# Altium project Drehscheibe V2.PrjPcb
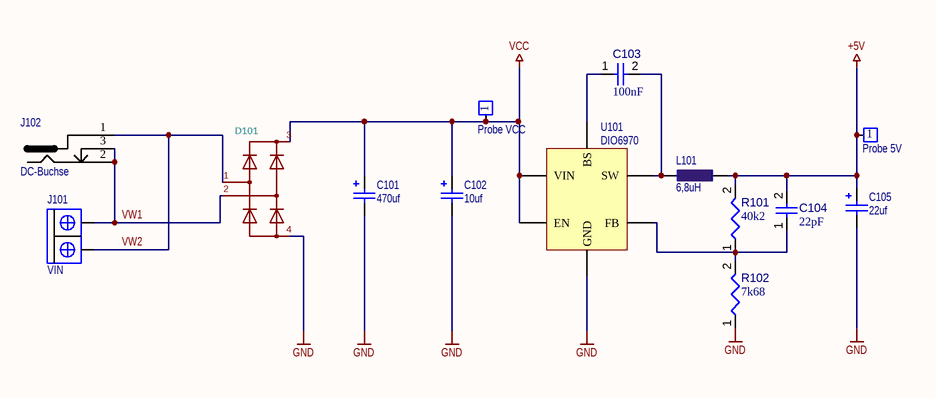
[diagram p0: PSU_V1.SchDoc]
7 sheets, 75 parts. Net scope: global (net labels, ports and power ports of the same name join across sheets).
Board file: Drehscheibe_V1.PcbDoc
Sheets:
  PSU_V1.SchDoc
  uC_V1.SchDoc
  Display_V1.SchDoc
  Stepper_V1.SchDoc
  Demudulation_V1.SchDoc
  Relais und Connector_V1.SchDoc
  Bediehneinheit_V1.SchDoc

## Sheet PSU_V1.SchDoc
size A4; SheetNumber: 1; SheetTotal: 7

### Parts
C101  470uf  [C_SMD_F-TYP]
C102  10uf  [C_SMD_C-TYP]
C103  value 100nF  [CAPC1608X90X40NL10T20]  (hidden comment: Capacitor 100 nF +/-10% 50 V 0603)
C104  22pF  [CAPC1608X90X40NL10T20]
C105  22uf  [C_SMD_C-TYP]
D101  *3D Model may have slightly different dimensions  [SO-DIL-ABS-4mm]  (value not drawn)
J101  VIN  [J_THT_Printklemme 2x]
J102  DC-Buchse  [J_THT_CJ-25]
L101  6,8uH  [L_SMD_NPIS42LS]
Probe_5V  #Wert  [SIP-1]  (value not drawn)
Probe_VCC  #Wert  [SIP-1]  (value not drawn)
R101  40k2  [RESC1608X55X25ML10T15]
R102  7k68  [RESC1608X55X25ML10T15]
U101  DIO6970  [SOT23-6]

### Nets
+5V: C104.2 C105.1 L101.1 Probe_5V.1 R101.2
GND: C101.2 C102.2 C105.2 D101.4(-) R102.1 U101.1(GND)
VCC: C101.1 C102.1 D101.3(+) Probe_VCC.1 U101.3(VIN) U101.5(EN)
VW1: D101.2(Input_~) J101.2 J102.2 J102.3
VW2: D101.1(Input_~) J101.1 J102.1
NetC103_1: C103.1 U101.6(BS)
NetC103_2: C103.2 L101.2 U101.2(SW)
NetC104_1: C104.1 R101.1 R102.2 U101.4(FB)

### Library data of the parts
C101 C102 C105 = C_SMD_ELK: SMD Elektrolytkondensator
C103 C104 = CMP-001-00017-6: Chip Capacitor, 100 nF, +/- 10%, 50 V, 0603 (1608 Metric); Voltage Rating: 50V; Capacitor Type: Ceramic
D101 = Bridge_1ph: ki_keywords: Bridge 1 phase; ki_description: Bridge_1_phase
J101 = J_THT_Printklemme 2x: Printklemme
J102 = J_THT_Hohlstecker
L101 = L_SMD_Spule: Spule SMD
Probe_5V Probe_VCC = J_THT_CON1: Stecker
R101 R102 = CMP-009-00017-5: Chip Resistor, 10 KOhm, +/- 1%, 01 W, -55 to 155 degC, 0603 (1608 Metric); Voltage Rating: 50V; Power: 100mW
U101 = U_DIO6970: Buckconverter

## Sheet uC_V1.SchDoc
size A4; SheetNumber: 2; SheetTotal: 7
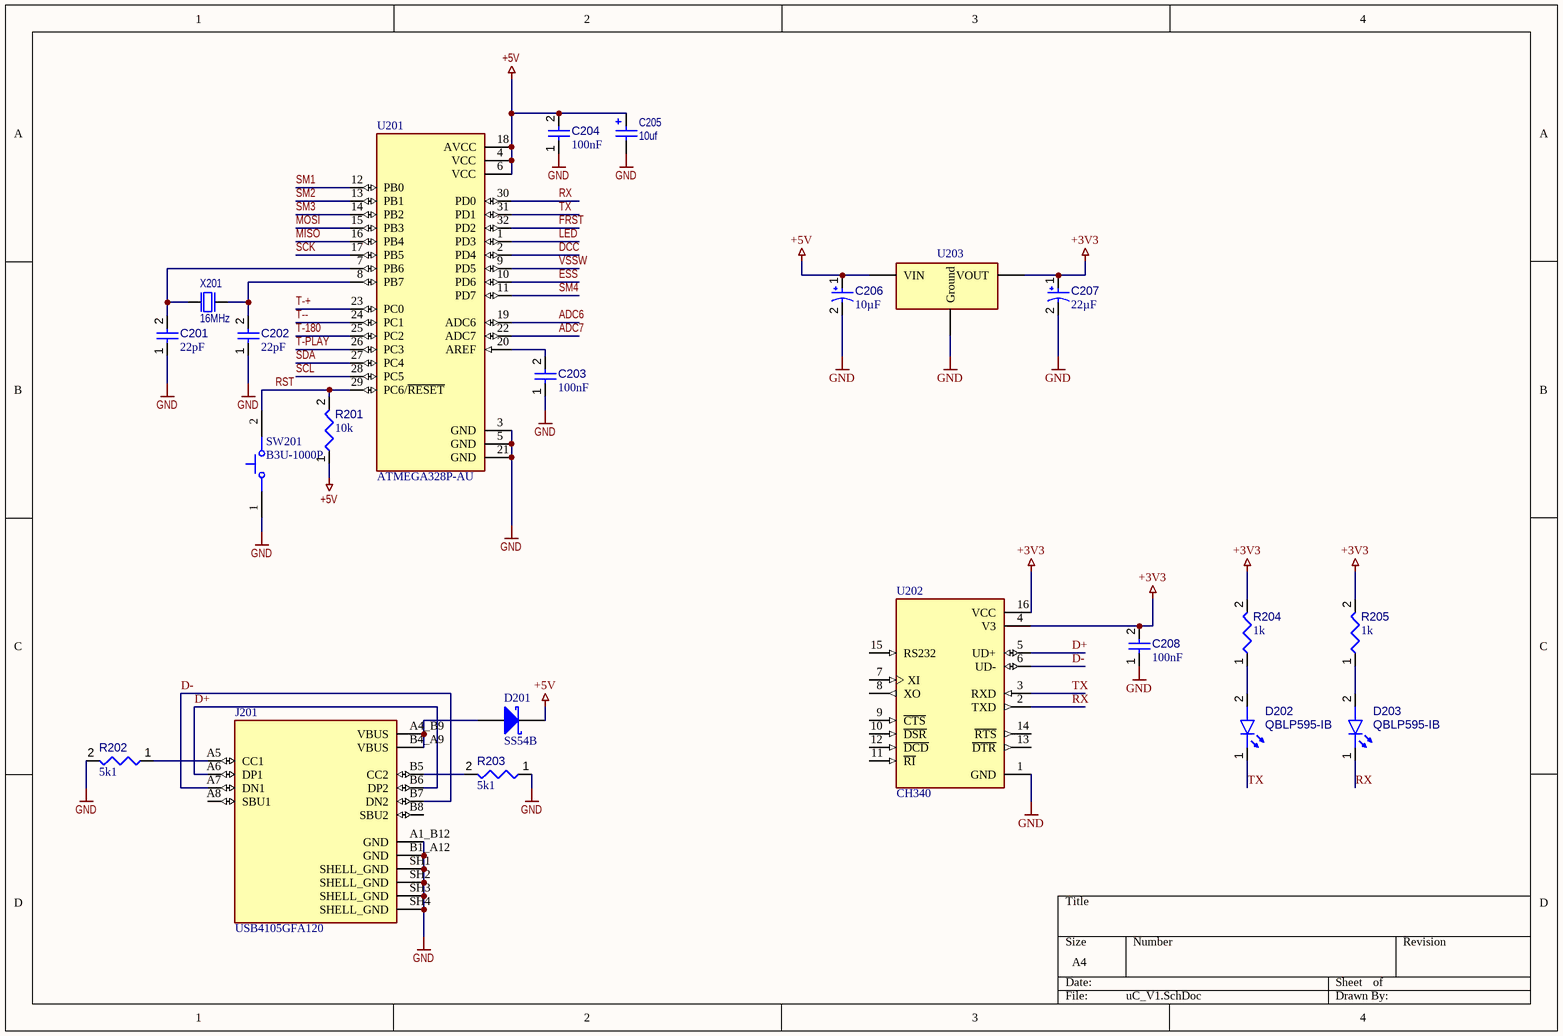
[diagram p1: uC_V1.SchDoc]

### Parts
C201  22pF  [CAPC1608X90X40NL10T20]
C202  22pF  [CAPC1608X90X40NL10T20]
C203  100nF  [CAPC1608X90X40NL10T20]
C204  100nF  [CAPC1608X90X40NL10T20]
C205  10uf  [C_SMD_C-TYP]
C206  value 10µF  [CAPMP3217X18-T_V]  (hidden comment: TAJA106K016RNJ)
C207  value 22µF  [VISH-7343-31_M]  (hidden comment: 293D226X9020D2TE3)
C208  value 100nF  [CAPC1608X90X40NL10T20]  (hidden comment: Capacitor 100 nF +/-10% 50 V 0603)
D201  SS54B  [JCET-SMB-2_M]
D202  QBLP595-IB  [QTB-QBLP595_V]
D203  QBLP595-IB  [QTB-QBLP595_V]
J201  USB4105GFA120  [GCT_USB4105GFA120]
R201  10k  [RESC1608X55X25ML10T15]
R202  5k1  [RESC1608X55X25ML10T15]
R203  5k1  [RESC1608X55X25ML10T15]
R204  value 1k  [RESC1608X55X25ML10T15]  (hidden comment: Resistor 1k +/-1% 0603 100 mW)
R205  value 1k  [RESC1608X55X25ML10T15]  (hidden comment: Resistor 1k +/-1% 0603 100 mW)
SW201  B3U-1000P  [OMRON-B3U-1000_V]
U201  ATMEGA328P-AU  [QFP80P900X900X120-32N]
U202  CH340  [SO-16]
U203  #Wert  [U_SMD_AMS1117]  (value not drawn)
X201  16MHz  [X_SMD_XTAL]

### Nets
+3V3: C207.1 C208.2 R204.2 R205.2 U202.4(V3) U202.16(VCC) U203.2(VOUT)
+5V: C204.2 C205.1 C206.1 D201.2(K) R201.1 U201.4(VCC) U201.6(VCC) U201.18(AVCC) U203.3(VIN)
GND: C201.1 C202.1 C203.1 C204.1 C205.2 C206.2 C207.2 C208.1 J201.A1_B12(GND) J201.B1_A12(GND) J201.SH1(SHELL_GND) J201.SH2(SHELL_GND) J201.SH3(SHELL_GND) J201.SH4(SHELL_GND) R202.2 R203.1 SW201.1 U201.3(GND) U201.5(GND) U201.21(GND) U202.1(GND) U203.1(Ground)
ADC6: U201.19(ADC6)
ADC7: U201.22(ADC7)
D+: J201.A6(DP1) J201.B6(DP2) U202.5(UD+)
D-: J201.A7(DN1) J201.B7(DN2) U202.6(UD-)
DCC: U201.2(PD4)
ESS: U201.10(PD6)
FRST: U201.32(PD2)
LED: U201.1(PD3)
MISO: U201.16(PB4)
MOSI: U201.15(PB3)
RST: R201.2 SW201.2 U201.29(PC6/~{RESET})
RX: D203.1(K) U201.30(PD0) U202.2(TXD)
SCK: U201.17(PB5)
SCL: U201.28(PC5)
SDA: U201.27(PC4)
SM1: U201.12(PB0)
SM2: U201.13(PB1)
SM3: U201.14(PB2)
SM4: U201.11(PD7)
T-180: U201.25(PC2)
T-+: U201.23(PC0)
T--: U201.24(PC1)
T-PLAY: U201.26(PC3)
TX: D202.1(K) U201.31(PD1) U202.3(RXD)
VSSW: U201.9(PD5)
NetC201_2: C201.2 U201.7(PB6) X201.1
NetC202_2: C202.2 U201.8(PB7) X201.2
NetC203_2: C203.2 U201.20(AREF)
NetD201_1: D201.1(A) J201.A4_B9(VBUS) J201.B4_A9(VBUS)
NetD202_2: D202.2(A) R204.1
NetD203_2: D203.2(A) R205.1
NetJ201_A5: J201.A5(CC1) R202.1
NetJ201_B5: J201.B5(CC2) R203.2

Not connected (* = marked no-connect by the designer): J201 A8(SBU1) B8(SBU2); U202 7(XI) 8(XO) 9(~{CTS}) 10(~{DSR}) 11(~{RI}) 12(~{DCD}) 13(~{DTR}) 14(~{RTS}) 15(RS232)

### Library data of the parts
C201-C204 C208 = CMP-001-00017-6: as C103 on sheet PSU_V1
C205 = C_SMD_ELK: SMD Elektrolytkondensator
C206 = CMP-001-00041-7: Standard Tantalum, 10 uF, +/- 10%, 16 V, -55 to 125 degC, 1206 (3216 Metric), RoHS, Tape and Reel; Manufacturer: AVX; Voltage Rating: 16V; ESR: 3Ohm
C207 = CMP-001-00021-7: Solid Tantalum Chip Capacitor, 22 uF, +/- 10%, 20 V, -55 to 125 degC, 2917 (7343 Metric), RoHS, Tape and Reel; Manufacturer: Vishay Semiconductor; Voltage Rating: 20V
D201 = CMP-004-00006-2: Schottky Barrier Rectifier, 40 V, 5 A, -55 to 150 degC, 2-Pin SMD; Manufacturer: JCET
D202 D203 = CMP-007-00042-3: Chip LED 0402, Blue, 0.02 A, 3.1 to 3.7 V, -40 to 80 degC, 2-Pin SMD, RoHS, Tape and Reel
J201 = USB4105GFA120: USB CONN, 2.0 TYPE C, RCPT, 16POS, SMT; USB Connector Type:USB Type C; USB Standard:USB 2.0; Gender:Receptacle; No. of Positions:16Positions; Connector Mounting:Surface Mount, Through Hole Mount; Orientation:Right Angle RoHS Compliant: Yes; MF: Global Connector Technology
R201-R203 = CMP-009-00017-5: as R101 on sheet PSU_V1
R204 R205 = CMP-009-00014-5: Chip Resistor, 1 KOhm, +/-1%, 0.1 W, -55 to 155 degC, 0603 (1608 Metric); Voltage Rating: 50V; Power: 100mW; Tolerance: 1%
SW201 = CMP-011-00000-2: Tactile Switch, SPST-NO, 0.05 A, 12 V, -25 to 70 degC, 2-Pin SMD, RoHS, Tape and Reel; Manufacturer: Omron Electronic Components; IP Rating: IP40; Current Rating: 50mA; Max Contact Resistance: 100mohm; Operating Force: 153gf; Throw Configuration: SPST; Resistance: 0.1Ohm; Max Voltage Rating (DC): 12V
U201 = ATMEGA328P-AU: MICROCONTROLLER MCU, 8 BIT, ATMEGA, 20MH; MICROCONTROLLER MCU, 8 BIT, ATMEGA, 20MHZ, TQFP-32; Controller Family/Series:ATmega; CPU Speed:20MHz; Program Memory Size:32KB; RAM Memory Size:2KB; No. of Pins:32Pins; MCU Case Style:TQFP; No. of I/O's:23I/O's; P; MF: Microchip Technology; MP: ATMEGA328PAU
U202 = IC_CH340: UART
U203 = U_SMD_AMS1117: Linearwandler; Manufacturer Part Number: AMS1117-3.3; Manufacturer: Advanced Monolithic Systems; Dropout Voltage: 1.1V; Output Type: Fixed; Nominal Supply Current: 5mA; Output Current: 1A; Output Voltage: 3.3V; Max Power Dissipation: 1.2W; Max Supply Voltage: 15V; Number Of Outputs: 1; Standoff Height: 0.64mm; Max Junction Temp: +125°C
X201 = X_SMD_Quarz: Quarz SMD

## Sheet Display_V1.SchDoc
size A4; SheetNumber: 3; SheetTotal: 7
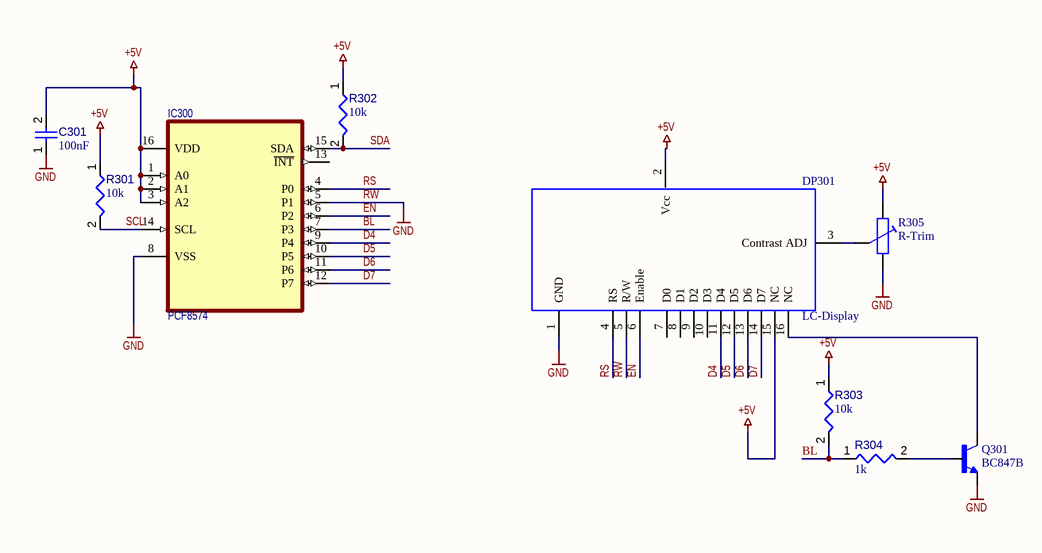
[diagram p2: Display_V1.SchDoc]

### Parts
C301  100nF  [CAPC1608X90X40NL10T20]
DP301  LC-Display  [V_THT_WM-C1610M]
IC300  PCF8574  [SO-16]
Q301  BC847B  [TRANS_BC847B]
R301  10k  [RESC1608X55X25ML10T15]
R302  10k  [RESC1608X55X25ML10T15]
R303  10k  [RESC1608X55X25ML10T15]
R304  value 1k  [RESC1608X55X25ML10T15]  (hidden comment: Resistor 1k +/-1% 0603 100 mW)
R305  R-Trim  [TP-.2/.4]

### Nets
+5V: C301.2 DP301.2(Vcc) DP301.15(NC) IC300.1(A0) IC300.2(A1) IC300.3(A2) IC300.16(VDD) R301.1 R302.1 R303.1 R305.2
GND: C301.1 DP301.1(GND) DP301.5(R/W) IC300.5(P1) IC300.8(VSS) Q301.2(E) R305.1  [also labelled RW]
BL: IC300.7(P3) R303.2 R304.1
D4: DP301.11(D4) IC300.9(P4)
D5: DP301.12(D5) IC300.10(P5)
D6: DP301.13(D6) IC300.11(P6)
D7: DP301.14(D7) IC300.12(P7)
EN: DP301.6(Enable) IC300.6(P2)
RS: DP301.4(RS) IC300.4(P0)
SCL: IC300.14(SCL) R301.2
SDA: IC300.15(SDA) R302.2
NetDP301_3: DP301.3(Contrast_ADJ) R305.3
NetDP301_16: DP301.16(NC) Q301.3(C)
NetQ301_1: Q301.1(B) R304.2

Not connected (* = marked no-connect by the designer): DP301 7(D0) 8(D1) 9(D2) 10(D3); IC300 13(~{INT})

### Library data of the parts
C301 = CMP-001-00017-6: as C103 on sheet PSU_V1
DP301 = V_THT_LCD Modul: LCD
IC300 = IC_PCF8574: I/O Expander
Q301 = BC847B: BJT, SOT-23, 45V, 100mA, NPN, 0.25W, 150Â°C; MF: Diotec Semiconductor
R301-R303 = CMP-009-00017-5: as R101 on sheet PSU_V1
R304 = CMP-009-00014-5: as R204 on sheet uC_V1
R305 = R-Trim: Potentiometer

## Sheet Stepper_V1.SchDoc
size A4; SheetNumber: 4; SheetTotal: 7
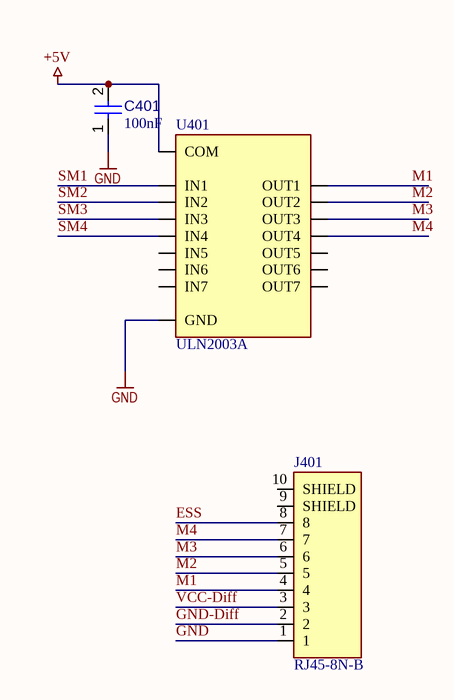
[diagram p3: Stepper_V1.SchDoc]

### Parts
C401  value 100nF  [CAPC1608X90X40NL10T20]  (hidden comment: Capacitor 100 nF +/-10% 50 V 0603)
J401  RJ45-8N-B  [TE_RJ45-8N-B]
U401  ULN2003A  [TSSOP-16-TI]

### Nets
+5V: C401.2 U401.9(COM)
GND: C401.1 J401.1 U401.8(GND)
ESS: J401.8
GND-Diff: J401.2
M1: J401.4 U401.16(OUT1)
M2: J401.5 U401.15(OUT2)
M3: J401.6 U401.14(OUT3)
M4: J401.7 U401.13(OUT4)
SM1: U401.1(IN1)
SM2: U401.2(IN2)
SM3: U401.3(IN3)
SM4: U401.4(IN4)
VCC-Diff: J401.3

Not connected (* = marked no-connect by the designer): J401 9(SHIELD) 10(SHIELD); U401 5(IN5) 6(IN6) 7(IN7) 10(OUT7) 11(OUT6) 12(OUT5)

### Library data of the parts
C401 = CMP-001-00017-6: as C103 on sheet PSU_V1
J401 = RJ45-8N-B: RJ Jack / Signal Line EMI/RFI Filters 6 TERM LOW PROFILE BLOCK INDUCTOR 8 PIN
U401 = ULN2003A: DARLINGTON ARRAY 7NPN, 2003, DIP16; Transistor Polarity:NPN; Collector Emitter Voltage V(br)ceo:50V; DC Collector Current:500mA; DC Current Gain hFE:1000; Operating Temperature Range:-20Â°C to +85Â°C; Transistor Case Style:DIP; No. of Pins:16; SVHC:No SVH; MF: STMicroelectronics

## Sheet Demudulation_V1.SchDoc
size A4; SheetNumber: 5; SheetTotal: 5
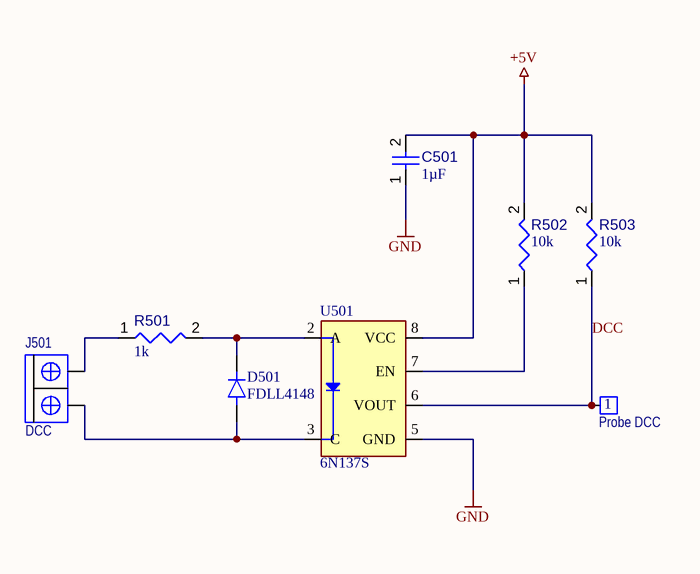
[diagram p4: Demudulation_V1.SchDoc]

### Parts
C501  value 1µF  [CAPC1608X90X40LL10T20]  (hidden comment: Capacitor 1 uF +/- 10% 25 V 0603)
D501  FDLL4148  [DIOMELF3414N]
J501  DCC  [J_THT_Printklemme 2x]
Probe_DCC  #Wert  [SIP-1]  (value not drawn)
R501  value 1k  [RESC1608X55X25ML10T15]  (hidden comment: Resistor 1k +/-1% 0603 100 mW)
R502  value 10k  [RESC1608X55X25ML10T15]  (hidden comment: Resistor 10k +/-1% 0603 100 mW)
R503  value 10k  [RESC1608X55X25ML10T15]  (hidden comment: Resistor 10k +/-1% 0603 100 mW)
U501  6N137S  [8-SMD]

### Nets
+5V: C501.2 R502.2 R503.2 U501.8(VCC)
GND: C501.1 U501.5(GND)
DCC: Probe_DCC.1 R503.1 U501.6(VOUT)
NetD501_A: D501.A J501.1 U501.3(C)
NetD501_C: D501.C R501.2 U501.2(A)
NetJ501_2: J501.2 R501.1
NetR502_1: R502.1 U501.7(EN)

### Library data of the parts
C501 = CMP-001-00005-6: Chip Capacitor, 1 uF, +/- 10%, 25 V, 0603 (1608 Metric); Capacitor Type: Ceramic; Voltage Rating: 25V
D501 = FDLL4148: Diode Standard 100 V 200mA Surface Mount SOD-80; MF: ON Semiconductor
J501 = J_THT_Printklemme 2x: Printklemme
Probe_DCC = J_THT_CON1: Stecker
R501 = CMP-009-00014-5: as R204 on sheet uC_V1
R502 R503 = CMP-009-00017-5: as R101 on sheet PSU_V1
U501 = 6N137S: Logic Output Optoisolator 15MBd Open Collector 5000Vrms 1 Channel 10kV/µs CMTI 8-SMD; MF: Lite-On Electronics

## Sheet Relais und Connector_V1.SchDoc
size A4; SheetNumber: 6; SheetTotal: 7
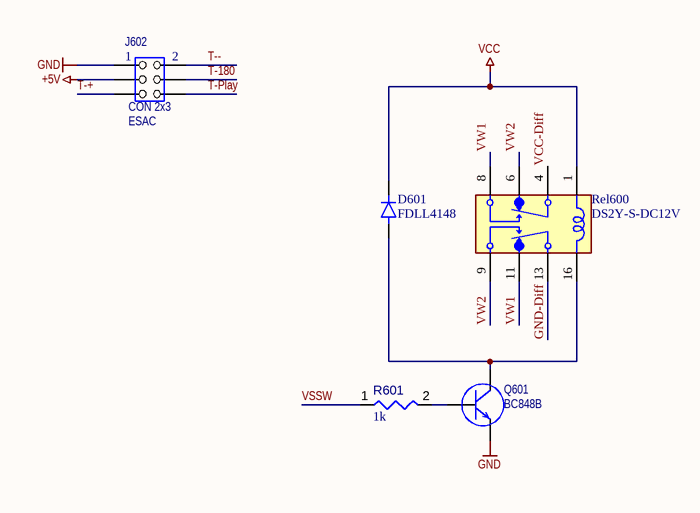
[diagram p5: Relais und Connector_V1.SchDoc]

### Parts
D601  FDLL4148  [DIOMELF3414N]
J602  CON 2x3  Use: ESAC  [J_2x3]
Q601  BC848B  [SOT-23]
R601  value 1k  [RESC1608X55X25ML10T15]  (hidden comment: Resistor 1k +/-1% 0603 100 mW)
Rel600  DS2Y-S-DC12V  [RELAY_DS2Y-S-DC12V]

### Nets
+5V: J602.3
GND: J602.1 Q601.2(E)
VCC: D601.C Rel600.1(POS)
GND-Diff: Rel600.13(COM2)
T-180: J602.4
T-+: J602.5
T--: J602.2
T-PLAY: J602.6
VCC-Diff: Rel600.4(COM1)
VSSW: R601.1
VW1: Rel600.8(NO1) Rel600.11(NC2)
VW2: Rel600.6(NC1) Rel600.9(NO2)
NetD601_A: D601.A Q601.3(C) Rel600.16(NEG)
NetQ601_1: Q601.1(B) R601.2

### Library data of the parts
D601 = FDLL4148: as D501 on sheet Demudulation_V1
J602 = J_THT_IDC 2x3: Stecker
Q601 = Q_SMD_NPN: NPN Transistor
R601 = CMP-009-00014-5: as R204 on sheet uC_V1
Rel600 = DS2Y-S-DC12V: General Purpose Relay DPDT _2 Form C_ Through Hole; MF: Panasonic Electric

## Sheet Bediehneinheit_V1.SchDoc
size A4; SheetNumber: 6; SheetTotal: 7
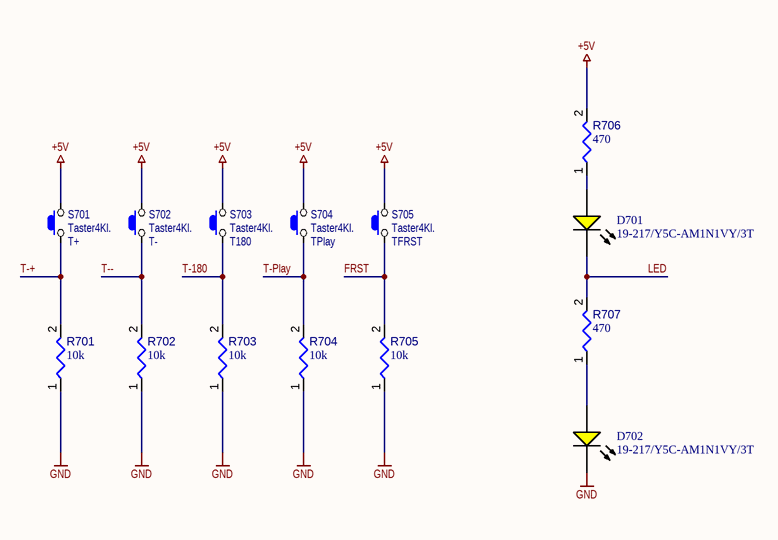
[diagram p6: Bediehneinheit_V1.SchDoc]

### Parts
D701  19-217/Y5C-AM1N1VY/3T  [EVRL-0603-2_V]
D702  19-217/Y5C-AM1N1VY/3T  [EVRL-0603-2_V]
R701  value 10k  [RESC1608X55X25ML10T15]  (hidden comment: Resistor 10k +/-1% 0603 100 mW)
R702  value 10k  [RESC1608X55X25ML10T15]  (hidden comment: Resistor 10k +/-1% 0603 100 mW)
R703  value 10k  [RESC1608X55X25ML10T15]  (hidden comment: Resistor 10k +/-1% 0603 100 mW)
R704  value 10k  [RESC1608X55X25ML10T15]  (hidden comment: Resistor 10k +/-1% 0603 100 mW)
R705  value 10k  [RESC1608X55X25ML10T15]  (hidden comment: Resistor 10k +/-1% 0603 100 mW)
R706  470  [RESC1608X55X25ML10T15]
R707  470  [RESC1608X55X25ML10T15]
S701  Taster4Kl.  Use: T+  [S_THT_Taster4kl.]
S702  Taster4Kl.  Use: T-  [S_THT_Taster4kl.]
S703  Taster4Kl.  Use: T180  [S_THT_Taster4kl.]
S704  Taster4Kl.  Use: TPlay  [S_THT_Taster4kl.]
S705  Taster4Kl.  Use: TFRST  [S_THT_Taster4kl.]

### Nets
+5V: R706.2 S701.2 S702.2 S703.2 S704.2 S705.2
GND: D702.2(K) R701.1 R702.1 R703.1 R704.1 R705.1
FRST: R705.2 S705.1
LED: D701.2(K) R707.2
T-180: R703.2 S703.1
T-+: R701.2 S701.1
T--: R702.2 S702.1
T-PLAY: R704.2 S704.1
NetD701_1: D701.1(A) R706.1
NetD702_1: D702.1(A) R707.1

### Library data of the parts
D701 D702 = CMP-007-00005-2: Chip LED, Yellow, 5 V, 25mA, -40 to 85 degC, 2-Pin SMD (0603), RoHS, Tape and Reel; Manufacturer: Everlight Electronics
R701-R707 = CMP-009-00017-5: as R101 on sheet PSU_V1
S701-S705 = S_THT_Taster: Taster

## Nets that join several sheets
+5V: PSU_V1 (5 pins), uC_V1 (9 pins), Display_V1 (11 pins), Stepper_V1 (C401.2 U401.9), Demudulation_V1 (C501.2 R502.2 R503.2 U501.8), Relais und Connector_V1 (J602.3), Bediehneinheit_V1 (6 pins)
GND: PSU_V1 (6 pins), uC_V1 (22 pins), Display_V1 (7 pins), Stepper_V1 (C401.1 J401.1 U401.8), Demudulation_V1 (C501.1 U501.5), Relais und Connector_V1 (J602.1 Q601.2), Bediehneinheit_V1 (6 pins)
VCC: PSU_V1 (6 pins), Relais und Connector_V1 (D601.C Rel600.1)
DCC: uC_V1 (U201.2), Demudulation_V1 (Probe_DCC.1 R503.1 U501.6)
ESS: uC_V1 (U201.10), Stepper_V1 (J401.8)
FRST: uC_V1 (U201.32), Bediehneinheit_V1 (R705.2 S705.1)
GND-Diff: Stepper_V1 (J401.2), Relais und Connector_V1 (Rel600.13)
LED: uC_V1 (U201.1), Bediehneinheit_V1 (D701.2 R707.2)
SCL: uC_V1 (U201.28), Display_V1 (IC300.14 R301.2)
SDA: uC_V1 (U201.27), Display_V1 (IC300.15 R302.2)
SM1: uC_V1 (U201.12), Stepper_V1 (U401.1)
SM2: uC_V1 (U201.13), Stepper_V1 (U401.2)
SM3: uC_V1 (U201.14), Stepper_V1 (U401.3)
SM4: uC_V1 (U201.11), Stepper_V1 (U401.4)
T-180: uC_V1 (U201.25), Relais und Connector_V1 (J602.4), Bediehneinheit_V1 (R703.2 S703.1)
T-+: uC_V1 (U201.23), Relais und Connector_V1 (J602.5), Bediehneinheit_V1 (R701.2 S701.1)
T--: uC_V1 (U201.24), Relais und Connector_V1 (J602.2), Bediehneinheit_V1 (R702.2 S702.1)
T-PLAY: uC_V1 (U201.26), Relais und Connector_V1 (J602.6), Bediehneinheit_V1 (R704.2 S704.1)
VCC-Diff: Stepper_V1 (J401.3), Relais und Connector_V1 (Rel600.4)
VSSW: uC_V1 (U201.9), Relais und Connector_V1 (R601.1)
VW1: PSU_V1 (D101.2 J101.2 J102.2 J102.3), Relais und Connector_V1 (Rel600.8 Rel600.11)
VW2: PSU_V1 (D101.1 J101.1 J102.1), Relais und Connector_V1 (Rel600.6 Rel600.9)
